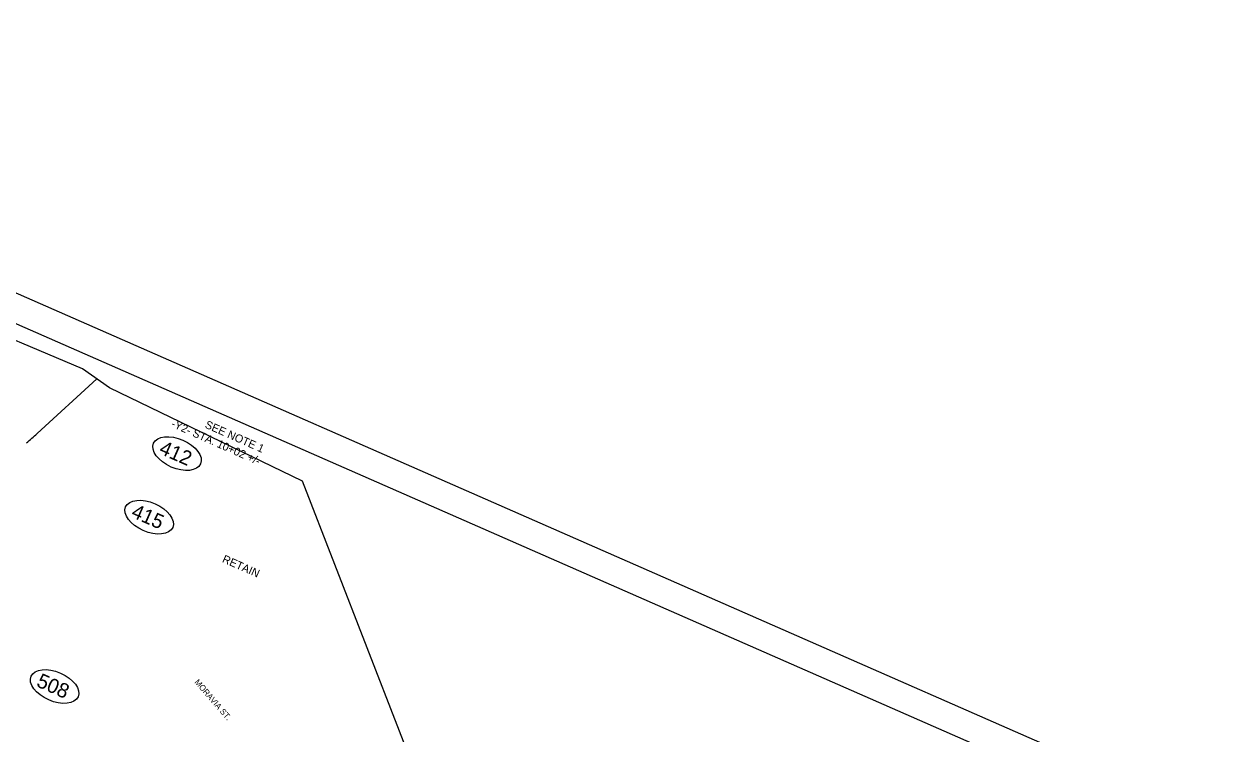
# Model space of a CAD drawing. Extents: x 1639021 to 1641149, y 842052 to 843739.
# Drawn here: x 1639988 to 1641009, y 843138 to 843738 of the extents above; entities that cross this region are included whole.
import ezdxf

# ---------------------------------------------------------------- set-up
doc = ezdxf.new("R2010")
doc.units = 0
for name, color, linetype in [('Default', 7, 'Continuous'), ('Exist Mkg Solid Double Yellow', 7, 'Continuous'), ('Prop Horizontal Alignment', 7, 'Continuous'), ('Prop Horizontal Alignment Tick Small', 7, 'Continuous'), ('Prop ROW Marker CELL', 7, 'Continuous'), ('Prop ROW Text', 7, 'Continuous'), ('Prop Sign E Speed Limit XX CELL', 7, 'Continuous')]:
    doc.layers.add(name, color=color, linetype=linetype)

msp = doc.modelspace()

# ---------------------------------------------------------------- linework, layer by layer
at = {"layer": 'Exist Mkg Solid Double Yellow'}
msp.add_line((1639999.4, 843391.9), (1640049.9, 843438.1), dxfattribs=at)
msp.add_arc((1638986, 844497.8), 1500, 312.0443, 312.4988, dxfattribs=at)
at = {"layer": 'Prop Horizontal Alignment Tick Small'}
msp.add_lwpolyline([(1639448.2, 842571.1), (1640243.3, 842221.8), (1640272.6, 842288.5), (1640399.9, 842232.5), (1640414.5, 842265.6), (1640431.7, 842258), (1640509.9, 842393.5), (1640578.7, 842512.8), (1640588.1, 842538), (1640589.1, 842540.8), (1640590.2, 842543.7), (1640594.1, 842554.2), (1640597.3, 842562.8), (1640602.2, 842575.9), (1640617.7, 842617.6), (1640629.1, 842742.4), (1640442.8, 843074.2), (1640333.3, 843069.3), (1640224, 843351.6), (1640060.6, 843430.6), (1640037.7, 843446.6), (1639929.5, 843492.2)], dxfattribs=at)
at = {"layer": 'Prop ROW Marker CELL'}
msp.add_lwpolyline([(1640976.5, 843047.7), (1639603.8, 843650.7), (1639181.1, 842688.4), (1640553.8, 842085.4)], close=True, dxfattribs=at)
at = {"layer": 'Prop ROW Text'}
msp.add_lwpolyline([(1639463.6, 843738.4), (1641009, 843059.5), (1640566.6, 842052.4), (1639021.2, 842731.3)], close=True, dxfattribs=at)
at = {"layer": 'Prop Sign E Speed Limit XX CELL'}
for centre in [(1640117.8, 843374.9), (1640094.2, 843321.1), (1640014.2, 843177.7)]:
    msp.add_ellipse(centre, major_axis=(-19.9, 8.7), ratio=0.571429, dxfattribs=at)

# ---------------------------------------------------------------- texts
at = {"layer": 'Default'}
for s, height, p in [('-Y2- STA. 10+02 +/-', 6.771, (1640112.2, 843397.8)), ('SEE NOTE 1', 6.77, (1640140.8, 843397)), ('RETAIN', 6.77, (1640155.4, 843283.2))]:
    msp.add_text(s, height=height, rotation=336.1242, dxfattribs=at).set_placement(p)
at = {"layer": 'Prop Horizontal Alignment'}
msp.add_text('MORAVIA ST.', height=5, rotation=310.7491, dxfattribs=at).set_placement((1640132.2, 843181.2))
at = {"layer": 'Prop Sign E Speed Limit XX CELL'}
for s, p in [('412', (1640101.8, 843375.2)), ('415', (1640078.2, 843321.5)), ('508', (1639998.1, 843178.1))]:
    msp.add_text(s, height=12.27, rotation=336.285, dxfattribs=at).set_placement(p)

doc.saveas('drawing.dxf')
